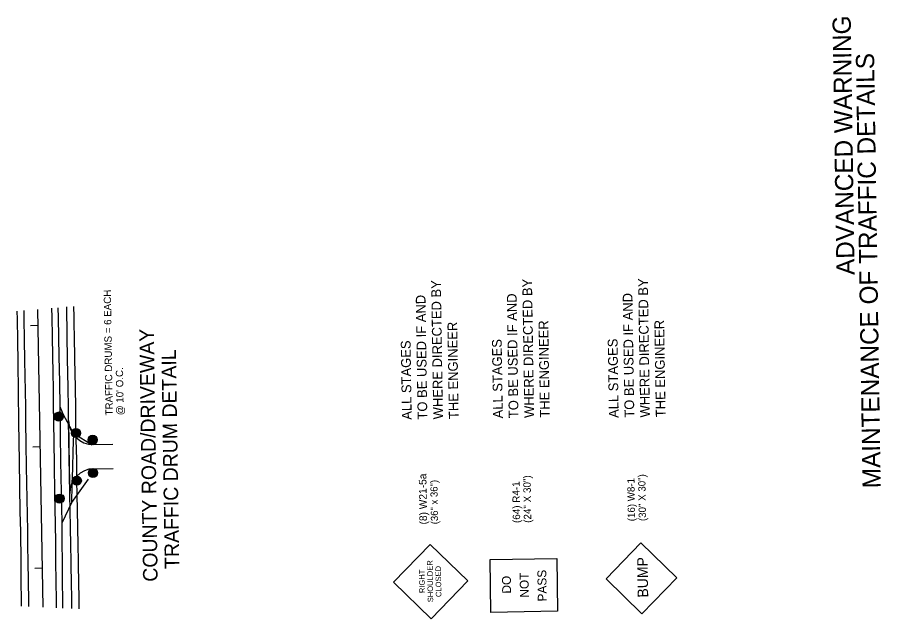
# Model space of a CAD drawing. Extents: x 1770018 to 1773492, y 718230 to 729141.
# Drawn here: x 1771297 to 1772008, y 721540 to 722036 of the extents above; entities that cross this region are included whole.
import ezdxf

# ---------------------------------------------------------------- set-up
doc = ezdxf.new("R2010")
doc.units = 0
for name, color, linetype in [('Default', 7, 'Continuous'), ('R_Dimension', 7, 'Continuous'), ('R_Drive', 7, 'Continuous'), ('R_Horz Alg', 7, 'Continuous'), ('R_MOT', 7, 'Continuous'), ('R_Proposed Road', 7, 'Continuous')]:
    doc.layers.add(name, color=color, linetype=linetype)

msp = doc.modelspace()

# ---------------------------------------------------------------- linework, layer by layer
at = {"layer": 'Default'}
for p, q in [((1771334.43, 721707.44), (1771327.2, 721707.33)), ((1771334.46, 721705.44), (1771327.23, 721705.33)), ((1771348.59, 721693.78), (1771341.36, 721693.66)), ((1771348.62, 721691.78), (1771341.39, 721691.66)), ((1771362.39, 721688.23), (1771355.16, 721688.12)), ((1771362.42, 721686.23), (1771355.19, 721686.12)), ((1771362.58, 721660.91), (1771355.35, 721660.8)), ((1771349.24, 721654.57), (1771342.02, 721654.45)), ((1771349.28, 721652.57), (1771342.05, 721652.45)), ((1771362.61, 721658.91), (1771355.38, 721658.8)), ((1771335.01, 721639.82), (1771327.78, 721639.71)), ((1771335.04, 721637.82), (1771327.81, 721637.71))]:
    msp.add_line(p, q, dxfattribs=at)
for points in [[(1771329.01, 721548.63), (1771328.92, 721554.62), (1771328.7, 721570.61), (1771328.47, 721586.6), (1771328.25, 721602.33), (1771328.02, 721618.06), (1771327.64, 721642.68), (1771327.26, 721667.31), (1771327.04, 721684.6), (1771326.81, 721701.9), (1771326.58, 721715.48), (1771326.35, 721729.07), (1771326.11, 721742.65), (1771325.88, 721756.24), (1771325.58, 721772.32), (1771325.29, 721788.4), (1771325.15, 721795.69)], [(1771334.22, 721548.39), (1771334.16, 721554.69), (1771333.99, 721570.69), (1771333.83, 721586.7), (1771333.65, 721602.67), (1771333.48, 721618.63), (1771333.26, 721631.31), (1771333.05, 721643.98), (1771332.84, 721656.66), (1771332.63, 721669.33), (1771332.33, 721691.86), (1771332.03, 721714.39), (1771331.61, 721734.94), (1771331.2, 721755.48), (1771330.89, 721771.82), (1771330.59, 721788.16), (1771330.44, 721796.14)], [(1771300.17, 721549.94), (1771300.11, 721554.65), (1771299.91, 721570.79), (1771299.7, 721586.92), (1771299.48, 721611.32), (1771299.03, 721628.21), (1771298.78, 721648.81), (1771298.54, 721669.41), (1771298.16, 721685.55), (1771297.78, 721701.69), (1771297.61, 721726.51), (1771297.44, 721751.34), (1771297.09, 721769.06), (1771296.74, 721786.77), (1771296.62, 721793.29)], [(1771306.16, 721549.67), (1771306.08, 721554.49), (1771305.85, 721570.64), (1771305.61, 721586.79), (1771305.4, 721599.41), (1771305.19, 721612.03), (1771304.95, 721625.25), (1771304.72, 721638.47), (1771304.49, 721651.69), (1771304.26, 721664.91), (1771304, 721683.51), (1771303.75, 721702.1), (1771303.55, 721714.69), (1771303.35, 721727.29), (1771303.14, 721739.88), (1771302.94, 721752.47), (1771302.62, 721769.77), (1771302.3, 721787.06), (1771302.17, 721793.76)], [(1771334.77, 721707.89), (1771332.03, 721714.39)], [(1771336.47, 721624.6), (1771341.52, 721635.6), (1771341.92, 721649.75), (1771342.33, 721663.9), (1771342.73, 721678.04), (1771343.14, 721692.19), (1771334.77, 721707.89)], [(1771358.35, 721682.88), (1771343.14, 721692.19)], [(1771341.52, 721635.6), (1771355.41, 721654.68)], [(1771333.48, 721618.63), (1771336.47, 721624.6)]]:
    msp.add_lwpolyline(points, dxfattribs=at)
for centre, radius in [((1771330.83, 721706.39), 3.75), ((1771330.83, 721706.39), 3.4), ((1771330.83, 721706.39), 2.9), ((1771330.83, 721706.39), 2.4), ((1771330.83, 721706.39), 1.9), ((1771330.83, 721706.39), 1.4), ((1771330.83, 721706.39), 0.898), ((1771330.83, 721706.39), 0.398), ((1771344.99, 721692.72), 3.75), ((1771344.99, 721692.72), 3.4), ((1771344.99, 721692.72), 2.9), ((1771344.99, 721692.72), 2.4), ((1771344.99, 721692.72), 1.9), ((1771344.99, 721692.72), 1.4), ((1771344.99, 721692.72), 0.898), ((1771344.99, 721692.72), 0.398), ((1771358.79, 721687.17), 3.75), ((1771358.79, 721687.17), 3.4), ((1771358.79, 721687.17), 2.9), ((1771358.79, 721687.17), 2.4), ((1771358.79, 721687.17), 1.9), ((1771358.79, 721687.17), 1.4), ((1771358.79, 721687.17), 0.898), ((1771358.79, 721687.17), 0.398), ((1771358.98, 721659.85), 3.75), ((1771358.98, 721659.85), 3.4), ((1771358.98, 721659.85), 2.9), ((1771358.98, 721659.85), 2.4), ((1771358.98, 721659.85), 1.9), ((1771358.98, 721659.85), 1.4), ((1771358.98, 721659.85), 0.898), ((1771358.98, 721659.85), 0.398), ((1771345.65, 721653.51), 3.75), ((1771345.65, 721653.51), 3.4), ((1771345.65, 721653.51), 2.9), ((1771345.65, 721653.51), 2.4), ((1771345.65, 721653.51), 1.9), ((1771345.65, 721653.51), 1.4), ((1771345.65, 721653.51), 0.898), ((1771345.65, 721653.51), 0.398), ((1771331.41, 721638.77), 3.75), ((1771331.41, 721638.77), 3.4), ((1771331.41, 721638.77), 2.9), ((1771331.41, 721638.77), 2.4), ((1771331.41, 721638.77), 1.9), ((1771331.41, 721638.77), 1.4), ((1771331.41, 721638.77), 0.898), ((1771331.41, 721638.77), 0.398)]:
    msp.add_circle(centre, radius, dxfattribs=at)
at = {"layer": 'R_Drive'}
for p, q in [((1771359.29, 721683.36), (1771375.28, 721683.63)), ((1771359.63, 721663.36), (1771375.63, 721663.63))]:
    msp.add_line(p, q, dxfattribs=at)
msp.add_lwpolyline([(1771339.97, 721643.02), (1771339.46, 721673.02), (1771338.95, 721703.01)], dxfattribs=at)
for centre, start, end in [((1771358.94, 721703.35), 180.98184, 270.98184), ((1771359.97, 721643.36), 90.98184, 180.98184)]:
    msp.add_arc(centre, 20, start, end, dxfattribs=at)
at = {"layer": 'R_Horz Alg'}
msp.add_line((1771313.37, 721794.7), (1771317.58, 721549.15), dxfattribs=at)
for points in [[(1771307.6, 721781.48), (1771313.6, 721781.59)], [(1771309.31, 721681.5), (1771315.31, 721681.6)], [(1771311.02, 721581.51), (1771317.02, 721581.62)]]:
    msp.add_lwpolyline(points, dxfattribs=at)
at = {"layer": 'R_MOT'}
for p, q in [((1771781.63, 721572.55), (1771810.36, 721602.18)), ((1771839.99, 721573.45), (1771810.36, 721602.18)), ((1771636.72, 721600.97), (1771606.55, 721569.85)), ((1771636.72, 721600.97), (1771667.82, 721570.8)), ((1771606.55, 721569.85), (1771637.67, 721539.67)), ((1771667.82, 721570.8), (1771637.67, 721539.67)), ((1771811.26, 721543.82), (1771781.63, 721572.55)), ((1771811.26, 721543.82), (1771839.99, 721573.45))]:
    msp.add_line(p, q, dxfattribs=at)
msp.add_lwpolyline([(1771686.17, 721588.53), (1771741.1, 721589.37), (1771741.77, 721545.79), (1771686.84, 721544.94)], close=True, dxfattribs=at)
at = {"layer": 'R_Proposed Road'}
for points in [[(1771341.6, 721548.06), (1771341.49, 721554.83), (1771341.48, 721555.09), (1771341.21, 721570.82), (1771341.2, 721571.25), (1771341.02, 721582.03), (1771340.94, 721586.82), (1771340.93, 721587.4), (1771340.71, 721600.02), (1771340.67, 721602.54), (1771340.49, 721612.63), (1771340.4, 721618.27), (1771340.27, 721625.85), (1771340.16, 721632.02), (1771340.04, 721639.08), (1771339.98, 721642.9), (1771339.82, 721652.3), (1771339.59, 721665.52), (1771339.55, 721667.52), (1771339.31, 721682.01), (1771339.27, 721684.11), (1771339.26, 721684.81), (1771338.96, 721702.1), (1771338.95, 721702.71), (1771338.74, 721715.3), (1771338.73, 721715.69), (1771338.52, 721727.89), (1771338.5, 721729.28), (1771338.45, 721732.01), (1771338.3, 721740.48), (1771338.26, 721742.86), (1771338.09, 721753.07), (1771338.03, 721756.45), (1771337.79, 721770.37), (1771337.75, 721772.53), (1771337.59, 721782), (1771337.5, 721787.66), (1771337.48, 721788.61), (1771337.34, 721796.72)], [(1771347.61, 721547.79), (1771347.48, 721554.93), (1771347.48, 721555.2), (1771347.21, 721570.93), (1771347.2, 721571.35), (1771347.02, 721582.13), (1771346.94, 721586.92), (1771346.93, 721587.5), (1771346.71, 721600.12), (1771346.67, 721602.65), (1771346.49, 721612.74), (1771346.4, 721618.38), (1771346.27, 721625.96), (1771346.16, 721632.12), (1771346.04, 721639.18), (1771345.98, 721643), (1771345.81, 721652.4), (1771345.59, 721665.62), (1771345.55, 721667.62), (1771345.3, 721682.12), (1771345.27, 721684.22), (1771345.26, 721684.91), (1771344.96, 721702.21), (1771344.95, 721702.81), (1771344.73, 721715.4), (1771344.73, 721715.79), (1771344.52, 721727.99), (1771344.49, 721729.38), (1771344.45, 721732.11), (1771344.3, 721740.58), (1771344.26, 721742.97), (1771344.09, 721753.17), (1771344.03, 721756.55), (1771343.79, 721770.47), (1771343.75, 721772.63), (1771343.59, 721782.1), (1771343.49, 721787.77), (1771343.48, 721788.71), (1771343.33, 721797.22)]]:
    msp.add_lwpolyline(points, dxfattribs=at)

# ---------------------------------------------------------------- texts
at = {"layer": 'Default'}
for s, height, p in [('ADVANCED WARNING ', 15, (1771986.49, 721823.16)), ('MAINTENANCE OF TRAFFIC DETAILS', 15, (1772007.98, 721647.37)), ('TRAFFIC DRUMS = 6 EACH', 6, (1771375.32, 721707.35)), ('COUNTY ROAD/DRIVEWAY', 12, (1771412.31, 721570.28)), ('TRAFFIC DRUM DETAIL', 12, (1771430.14, 721580.85)), ("@ 10' O.C.", 6, (1771384.31, 721707.49))]:
    msp.add_text(s, height=height, rotation=90.88269, dxfattribs=at).set_placement(p)
at = {"layer": 'R_Dimension'}
for s, p in [('WHERE DIRECTED BY', (1771647.33, 721704.15)), ('WHERE DIRECTED BY', (1771722.4, 721705.31)), ('WHERE DIRECTED BY', (1771817.83, 721705.68)), ('TO BE USED IF AND', (1771634.45, 721703.96)), ('TO BE USED IF AND', (1771709.53, 721705.11)), ('TO BE USED IF AND', (1771804.95, 721705.48)), ('THE ENGINEER', (1771660.2, 721704.35)), ('THE ENGINEER', (1771735.28, 721705.51)), ('THE ENGINEER', (1771830.7, 721705.88)), ('ALL STAGES', (1771621.58, 721703.76)), ('ALL STAGES', (1771696.65, 721704.91)), ('ALL STAGES', (1771792.07, 721705.28))]:
    msp.add_text(s, height=8, rotation=90.88269, dxfattribs=at).set_placement(p)
at = {"layer": 'R_MOT'}
for s, height, rotation, p in [('(8) W21-5a', 6.273, 90.88269, (1771634.26, 721617.45)), ('(36" x 36")', 5.88, 90.88269, (1771643.28, 721617.59)), ('(64) R4-1', 6.084, 90.88269, (1771710.96, 721618.64)), ('(24" X 30")', 6.084, 90.88269, (1771720.09, 721618.78)), ('(16) W8-1', 6.002, 90.88269, (1771805.62, 721620.09)), ('(30" X 30")', 6.0016, 90.88269, (1771814.62, 721620.23)), ('BUMP', 8.642, 90.88269, (1771816.41, 721557.17)), ('SHOULDER', 4.515, 90.88272, (1771639.28, 721553.32)), ('CLOSED', 4.516, 90.88326, (1771645.99, 721557.6)), ('RIGHT', 4.516, 90.88314, (1771632.39, 721560.83)), ('DO', 7.312, 90.88269, (1771703.43, 721560.49)), ('NOT', 7.312, 90.88269, (1771718.11, 721557.14)), ('PASS', 7.312, 90.88269, (1771732.79, 721553.97))]:
    msp.add_text(s, height=height, rotation=rotation, dxfattribs=at).set_placement(p)

doc.saveas('drawing.dxf')
